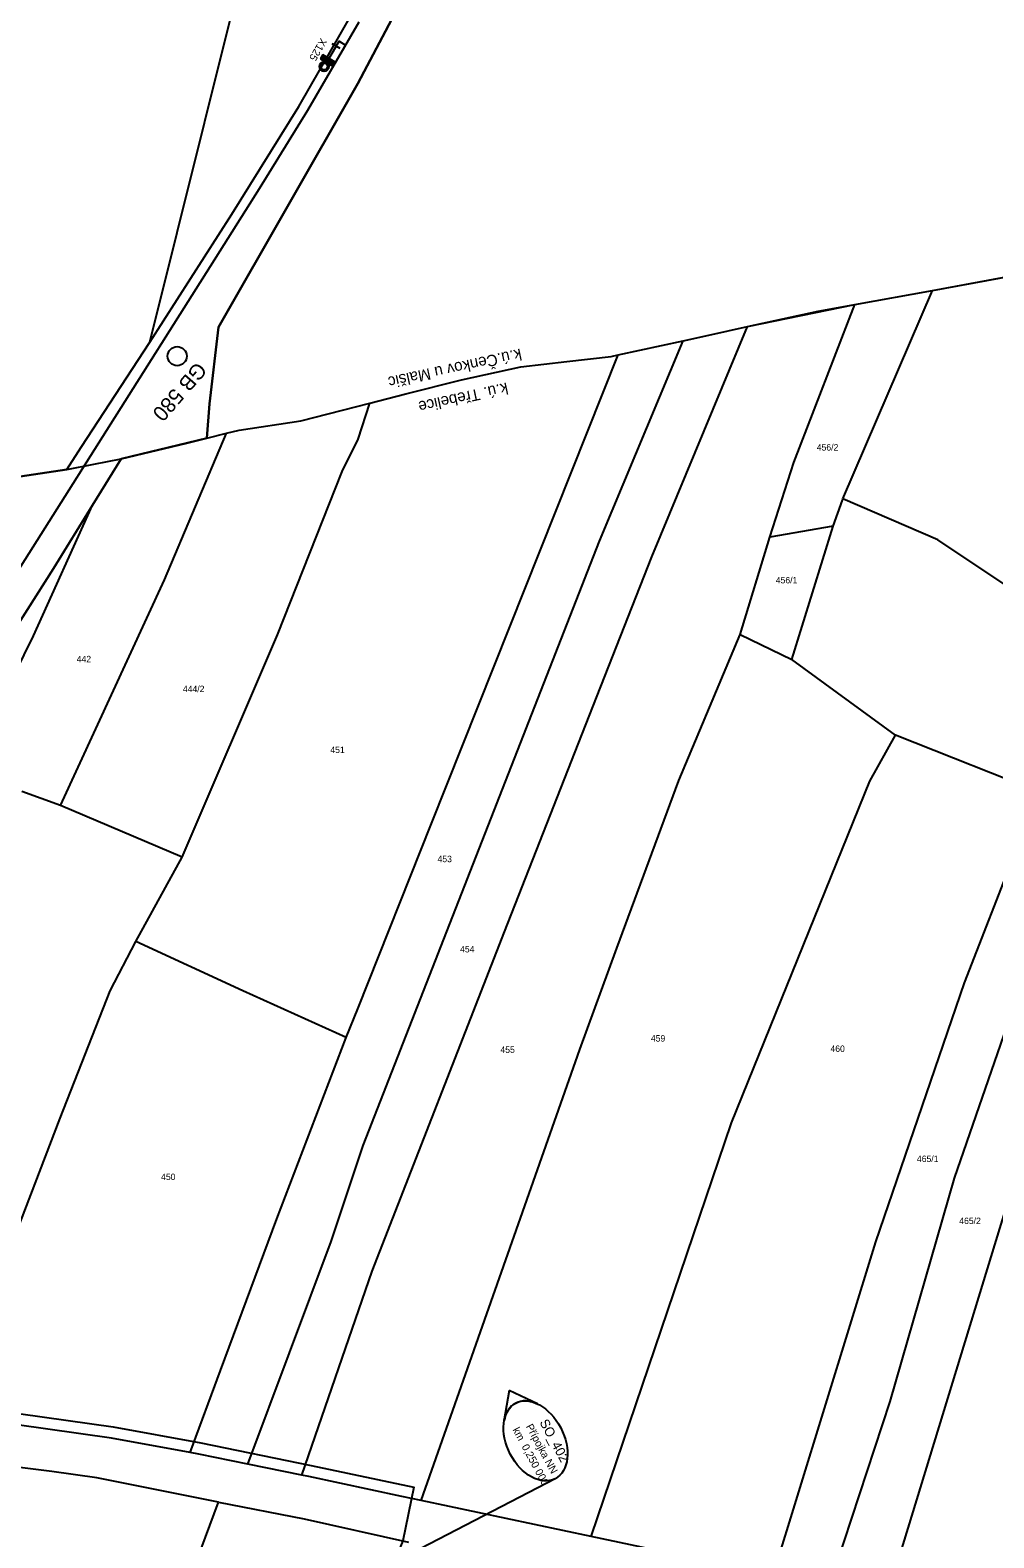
# Model space of a CAD drawing. Extents: x -746176 to -739709, y -1128407 to -1124482.
# Drawn here: x -743038.9 to -742784.8, y -1127139.9 to -1126742.1 of the extents above; entities that cross this region are included whole.
import ezdxf

# ---------------------------------------------------------------- set-up
doc = ezdxf.new("R2010")
doc.units = 0
for name, color, linetype in [('_Násyp', 7, 'Continuous'), ('_TRASA_vedení kabelu_CEZ', 7, 'Continuous'), ('_Zabezpečovací zařízení', 7, 'Continuous'), ('_Zabezpečovací zařízení_trasa', 7, 'Continuous'), ('bublina_růžová_230_čára_tenká', 7, 'Continuous'), ('bublina_růžová_230_čára_tučná', 7, 'Continuous'), ('Hranice parcel', 7, 'Continuous'), ('Parcelní čísla', 7, 'Continuous'), ('Vrstva 53', 7, 'Continuous'), ('Vrstva 55', 7, 'Continuous'), ('ŽBP', 7, 'Continuous')]:
    doc.layers.add(name, color=color, linetype=linetype)

msp = doc.modelspace()

# ---------------------------------------------------------------- linework, layer by layer
at = {"layer": '_TRASA_vedení kabelu_CEZ'}
msp.add_lwpolyline([(-743154.26, -1127082.61), (-743159.25, -1127091.79), (-743078.98, -1127101.9), (-743017.04, -1127110.61), (-742993.93, -1127114.82), (-742964.82, -1127120.76), (-742937.74, -1127126.54), (-742940.65, -1127140.7), (-742943, -1127146.4)], dxfattribs=at)
at = {"layer": '_Zabezpečovací zařízení'}
for p, q in [((-742958.23, -1126746.33), (-742960.75, -1126750.66)), ((-742957.15, -1126746.96), (-742959.31, -1126745.71)), ((-742961.74, -1126748.63), (-742962.37, -1126749.71)), ((-742962.37, -1126749.71), (-742959.13, -1126751.6)), ((-742962.31, -1126749.61), (-742962.27, -1126749.77)), ((-742962.03, -1126749.13), (-742961.79, -1126750.05)), ((-742961.75, -1126748.64), (-742961.3, -1126750.34)), ((-742958.5, -1126750.52), (-742961.74, -1126748.63)), ((-742961.27, -1126748.91), (-742960.82, -1126750.62)), ((-742960.78, -1126749.19), (-742960.51, -1126750.24)), ((-742960.51, -1126750.24), (-742960.33, -1126750.9)), ((-742960.3, -1126749.47), (-742960.22, -1126749.75)), ((-742960.22, -1126749.75), (-742959.85, -1126751.18)), ((-742959.81, -1126749.76), (-742959.36, -1126751.46)), ((-742959.33, -1126750.04), (-742958.98, -1126751.35)), ((-742959.13, -1126751.6), (-742958.5, -1126750.52)), ((-742958.84, -1126750.32), (-742958.7, -1126750.86))]:
    msp.add_line(p, q, dxfattribs=at)
for radius in [1.25, 0.875]:
    msp.add_circle((-742961.38, -1126751.74), radius, dxfattribs=at)
at = {"layer": '_Zabezpečovací zařízení_trasa'}
for points in [[(-742952.25, -1126740.02), (-742965.82, -1126763.29), (-742978.53, -1126783.97), (-742991.5, -1126804.49), (-743018.82, -1126847.74), (-743049.28, -1126895.95)], [(-742958.23, -1126746.33), (-742957.49, -1126745.05), (-742955.77, -1126746.05)]]:
    msp.add_lwpolyline(points, dxfattribs=at)
at = {"layer": 'bublina_růžová_230_čára_tenká'}
msp.add_line((-742900.48, -1127124.28), (-742943, -1127146.4), dxfattribs=at)
at = {"layer": 'bublina_růžová_230_čára_tučná'}
for p, q in [((-742912.6, -1127100.99), (-742913.98, -1127109.13)), ((-742912.6, -1127100.99), (-742913.98, -1127109.13)), ((-742905.14, -1127104.53), (-742912.6, -1127100.99)), ((-742905.14, -1127104.53), (-742912.6, -1127100.99))]:
    msp.add_line(p, q, dxfattribs=at)
msp.add_ellipse((-742905.68, -1127114.3), major_axis=(5.19, -9.98), ratio=0.666667, dxfattribs=at)
msp.add_ellipse((-742905.68, -1127114.3), major_axis=(-5.19, 9.98), ratio=0.666473, start_param=5.557317, end_param=7.009053, dxfattribs=at)
at = {"layer": 'Hranice parcel'}
for p, q in [((-742824.58, -1126865.74), (-742800.98, -1126810.76)), ((-742821.45, -1126814.49), (-742800.98, -1126810.76)), ((-742821.45, -1126814.49), (-742800.98, -1126810.76)), ((-742883.83, -1126827.8), (-742866.72, -1126824.05)), ((-742883.83, -1126827.8), (-742866.72, -1126824.05)), ((-742992.38, -1126849.75), (-742987.15, -1126848.45)), ((-742992.38, -1126849.75), (-742987.15, -1126848.45)), ((-743022.51, -1126867.46), (-743014.97, -1126855.23)), ((-743045.12, -1126860.39), (-743029.24, -1126857.99)), ((-743045.12, -1126860.39), (-743029.24, -1126857.99)), ((-742827.15, -1126873), (-742843.85, -1126875.84)), ((-742838.1, -1126908.15), (-742827.15, -1126873)), ((-742851.71, -1126901.51), (-742843.85, -1126875.84)), ((-742851.71, -1126901.51), (-742838.1, -1126908.15)), ((-742810.76, -1126928.12), (-742838.1, -1126908.15)), ((-743030.98, -1126946.66), (-743041.11, -1126943.01)), ((-742998.88, -1126960.31), (-743030.98, -1126946.66)), ((-743011.05, -1126982.56), (-742998.88, -1126960.31)), ((-742967.31, -1127123.32), (-742981.52, -1127120.42)), ((-742891, -1127139.53), (-742935.81, -1127130.03)), ((-743016.08, -1127203.24), (-742989.3, -1127130.42))]:
    msp.add_line(p, q, dxfattribs=at)
for points in [[(-742992.38, -1126849.75), (-742991.64, -1126840.74), (-742989.3, -1126820.48), (-742952.51, -1126756.2), (-742924.84, -1126703.65), (-742908.96, -1126671.82), (-742895.27, -1126638.64), (-742882.51, -1126605.32), (-742871.12, -1126571.44), (-742860.04, -1126536.32), (-742843.66, -1126479.02), (-742830.4, -1126433.39), (-742814.62, -1126379.12)], [(-743007.42, -1126824.46), (-742978.43, -1126708.24), (-742923.29, -1126571.7), (-742877.43, -1126445.3)], [(-743007.42, -1126824.46), (-742985.76, -1126790.66), (-742968.06, -1126762.29), (-742948.34, -1126727.71), (-742946, -1126723.19), (-742932.62, -1126697.32), (-742918.31, -1126667.03), (-742904.27, -1126634.33), (-742891.32, -1126601.26), (-742885.74, -1126585.7), (-742879.44, -1126568.16), (-742868.17, -1126534.02), (-742855.85, -1126489.61), (-742844.85, -1126450.33)], [(-742800.98, -1126810.76), (-742782.52, -1126807.39), (-742769.01, -1126804.93)], [(-742800.98, -1126810.76), (-742782.52, -1126807.39), (-742769.01, -1126804.93)], [(-742849.79, -1126820.34), (-742831.12, -1126816.25), (-742821.45, -1126814.49)], [(-742849.79, -1126820.34), (-742831.12, -1126816.25), (-742821.45, -1126814.49)], [(-742843.85, -1126875.84), (-742837.53, -1126856.16), (-742821.45, -1126814.49)], [(-742967.31, -1127123.32), (-742948.78, -1127069.51), (-742913.81, -1126980), (-742891.52, -1126923.09), (-742875.03, -1126881.03), (-742849.79, -1126820.34)], [(-742866.72, -1126824.05), (-742859.97, -1126822.57), (-742849.79, -1126820.34)], [(-742866.72, -1126824.05), (-742859.97, -1126822.57), (-742849.79, -1126820.34)], [(-743029.24, -1126857.99), (-743025.53, -1126852.15), (-743007.42, -1126824.46)], [(-742981.52, -1127120.42), (-742959.53, -1127061.71), (-742951.08, -1127036.33), (-742935.17, -1126995.67), (-742888.83, -1126876.94), (-742866.72, -1126824.05)], [(-742955.58, -1127007.86), (-742952.5, -1127000.35), (-742933.06, -1126951.45), (-742883.83, -1126827.8)], [(-742949.34, -1126840.52), (-742939.84, -1126838.09), (-742925.21, -1126834.34), (-742909.52, -1126830.92), (-742897.44, -1126829.55), (-742885.68, -1126828.21), (-742883.83, -1126827.8)], [(-742949.34, -1126840.52), (-742939.84, -1126838.09), (-742925.21, -1126834.34), (-742909.52, -1126830.92), (-742897.44, -1126829.55), (-742885.68, -1126828.21), (-742883.83, -1126827.8)], [(-742998.88, -1126960.31), (-742973.7, -1126901.64), (-742956.68, -1126858.57), (-742952.43, -1126850.05), (-742949.34, -1126840.52)], [(-742987.15, -1126848.45), (-742983.82, -1126847.62), (-742967.54, -1126845.19), (-742949.34, -1126840.52)], [(-742987.15, -1126848.45), (-742983.82, -1126847.62), (-742967.54, -1126845.19), (-742949.34, -1126840.52)], [(-743030.98, -1126946.66), (-743003.48, -1126887.11), (-742987.15, -1126848.45)], [(-743014.97, -1126855.23), (-742997.62, -1126851.06), (-742992.38, -1126849.75)], [(-743014.97, -1126855.23), (-742997.62, -1126851.06), (-742992.38, -1126849.75)], [(-743029.24, -1126857.99), (-743022.12, -1126856.61), (-743014.97, -1126855.23)], [(-743029.24, -1126857.99), (-743022.12, -1126856.61), (-743014.97, -1126855.23)], [(-743063.8, -1126932.98), (-743032.8, -1126884.17), (-743022.51, -1126867.46)], [(-743055.18, -1126936.67), (-743038.05, -1126901.87), (-743022.51, -1126867.46)], [(-742827.15, -1126873), (-742824.73, -1126866.08), (-742824.58, -1126865.74)], [(-742750.49, -1126903.46), (-742763.27, -1126898.97), (-742762.5, -1126896.14), (-742781.04, -1126889), (-742799.57, -1126876.62), (-742824.58, -1126865.74)], [(-742935.81, -1127130.03), (-742894, -1127011.08), (-742884.2, -1126984.32), (-742867.91, -1126940.04), (-742851.71, -1126901.51)], [(-742891, -1127139.53), (-742854.01, -1127030.4), (-742817.51, -1126940.24), (-742810.76, -1126928.12)], [(-742778.92, -1126958.45), (-742777.55, -1126954.82), (-742770.36, -1126944.15), (-742810.76, -1126928.12)], [(-742842.98, -1127149.74), (-742815.95, -1127061.82), (-742792.49, -1126993.43), (-742778.92, -1126958.45)], [(-742828.27, -1127153.14), (-742812.1, -1127103.89), (-742795.18, -1127045), (-742777.21, -1126993.06), (-742763.72, -1126962.33)], [(-742813.25, -1127156.61), (-742778.25, -1127042.21), (-742763.25, -1126998.63), (-742748.81, -1126966.24)], [(-743059.24, -1127107.7), (-743046.52, -1127069.6), (-743031.05, -1127029.12), (-743017.87, -1126995.55), (-743011.05, -1126982.56)], [(-742955.58, -1127007.86), (-742982.82, -1126995.58), (-743011.05, -1126982.56)], [(-742996.77, -1127117.36), (-742988.72, -1127095.72), (-742973.91, -1127055.72), (-742955.58, -1127007.86)], [(-742996.77, -1127117.36), (-743017.52, -1127113.57), (-743059.24, -1127107.7)], [(-742981.52, -1127120.42), (-742994.5, -1127117.77), (-742996.77, -1127117.36)], [(-742989.3, -1127130.42), (-743021.39, -1127124.08), (-743033.19, -1127122.41), (-743048.8, -1127120.46)], [(-742935.81, -1127130.03), (-742940.93, -1127128.94), (-742965.43, -1127123.7), (-742967.31, -1127123.32)], [(-742989.3, -1127130.42), (-742966.69, -1127134.89), (-742939.19, -1127141.02)], [(-742842.98, -1127149.74), (-742843.7, -1127149.57), (-742891, -1127139.53)]]:
    msp.add_lwpolyline(points, dxfattribs=at)
at = {"layer": 'Vrstva 53'}
for points in [[(-743029.24, -1126857.99), (-743025.53, -1126852.15), (-743007.42, -1126824.46), (-742985.76, -1126790.66), (-742968.06, -1126762.29), (-742948.34, -1126727.71), (-742946, -1126723.19), (-742932.62, -1126697.32), (-742918.31, -1126667.03), (-742904.27, -1126634.33), (-742891.32, -1126601.26), (-742885.74, -1126585.7), (-742879.44, -1126568.16), (-742868.17, -1126534.02), (-742855.85, -1126489.61), (-742844.85, -1126450.33), (-742843.78, -1126446.5), (-742832.7, -1126409.87), (-742821.63, -1126373.24)], [(-742814.62, -1126379.12), (-742830.4, -1126433.39), (-742843.66, -1126479.02), (-742860.04, -1126536.32), (-742871.12, -1126571.44), (-742882.51, -1126605.32), (-742895.27, -1126638.64), (-742908.96, -1126671.82), (-742924.84, -1126703.65), (-742952.51, -1126756.2), (-742989.3, -1126820.48), (-742991.64, -1126840.74), (-742992.38, -1126849.75)], [(-742992.38, -1126849.75), (-743014.97, -1126855.23), (-743022.51, -1126867.46), (-743032.8, -1126884.17), (-743063.8, -1126932.98)], [(-743045.12, -1126860.39), (-743029.24, -1126857.99)]]:
    msp.add_lwpolyline(points, dxfattribs=at)
at = {"layer": 'Vrstva 55'}
for points in [[(-743029.24, -1126857.99), (-743022.12, -1126856.61), (-743014.97, -1126855.23), (-742997.62, -1126851.06), (-742992.38, -1126849.75), (-742987.15, -1126848.45), (-742983.82, -1126847.62), (-742967.54, -1126845.19), (-742949.34, -1126840.52), (-742939.84, -1126838.09), (-742925.21, -1126834.34), (-742909.52, -1126830.92), (-742897.44, -1126829.55), (-742885.68, -1126828.21), (-742883.83, -1126827.8), (-742866.72, -1126824.05), (-742859.97, -1126822.57), (-742849.79, -1126820.34), (-742821.45, -1126814.49), (-742800.98, -1126810.76), (-742769.01, -1126804.93)], [(-743029.24, -1126857.99), (-743045.12, -1126860.39), (-743063.79, -1126864.46), (-743081.5, -1126868.29), (-743094.61, -1126871.12), (-743096.16, -1126871.29), (-743108.94, -1126872.71), (-743135.6, -1126876), (-743141.43, -1126876.56), (-743166.37, -1126878.96), (-743178.08, -1126880.08), (-743209.04, -1126886.14), (-743225.02, -1126889.27), (-743239.29, -1126892.07)]]:
    msp.add_lwpolyline(points, dxfattribs=at)
at = {"layer": 'ŽBP'}
msp.add_circle((-743000.16, -1126828.12), 2.52, dxfattribs=at)

# ---------------------------------------------------------------- texts
at = {"layer": '_Násyp'}
for s, height, p in [('Přípojka NN', 2, (-742908.27, -1127110.47)), ('SO_402', 2.5, (-742904.68, -1127109.39)), ('km  0,250 000', 2, (-742911.78, -1127111.35))]:
    msp.add_text(s, height=height, rotation=298.159, dxfattribs=at).set_placement(p)
at = {"layer": '_Zabezpečovací zařízení'}
msp.add_text('X125', height=2, rotation=239.923, dxfattribs=at).set_placement((-742962.3, -1126744.05))
at = {"layer": 'Parcelní čísla'}
for s, p in [('456/2', (-742831.49, -1126853.03)), ('456/1', (-742842.3, -1126888.07)), ('442', (-743026.66, -1126908.89)), ('444/2', (-742998.66, -1126916.76)), ('451', (-742959.78, -1126932.83)), ('453', (-742931.51, -1126961.62)), ('454', (-742925.56, -1126985.43)), ('455', (-742914.92, -1127011.93)), ('459', (-742875.24, -1127008.95)), ('460', (-742827.88, -1127011.68)), ('465/1', (-742805.07, -1127040.72)), ('450', (-743004.41, -1127045.48)), ('465/2', (-742793.91, -1127057.09))]:
    msp.add_text(s, height=1.7, dxfattribs=at).set_placement(p)
at = {"layer": 'Vrstva 55'}
for s, rotation, p in [('k.ú.Čenkov u Malšic', 192.1813, (-742909.68, -1126826.1)), ('k.ú. Třebelice', 192.2966, (-742913.27, -1126835.05))]:
    msp.add_text(s, height=3, rotation=rotation, dxfattribs=at).set_placement(p)
at = {"layer": 'ŽBP'}
msp.add_text('GB 580', height=4, rotation=228.8931, dxfattribs=at).set_placement((-742995.02, -1126829.39))

doc.saveas('drawing.dxf')
